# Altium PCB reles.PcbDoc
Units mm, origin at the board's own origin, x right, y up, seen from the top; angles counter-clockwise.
Board outline 127 x 101.6 mm, 2 copper layers (Top Layer, Bottom Layer); 7 components, 7 nets, 21 pads, 0 vias.
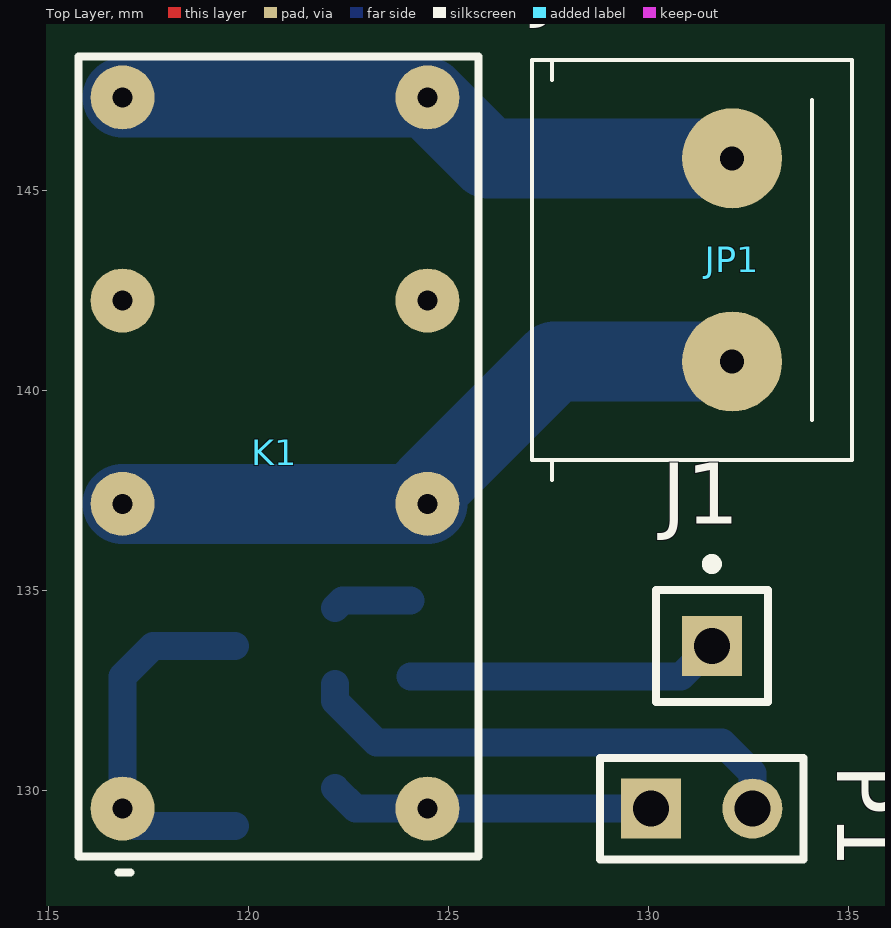
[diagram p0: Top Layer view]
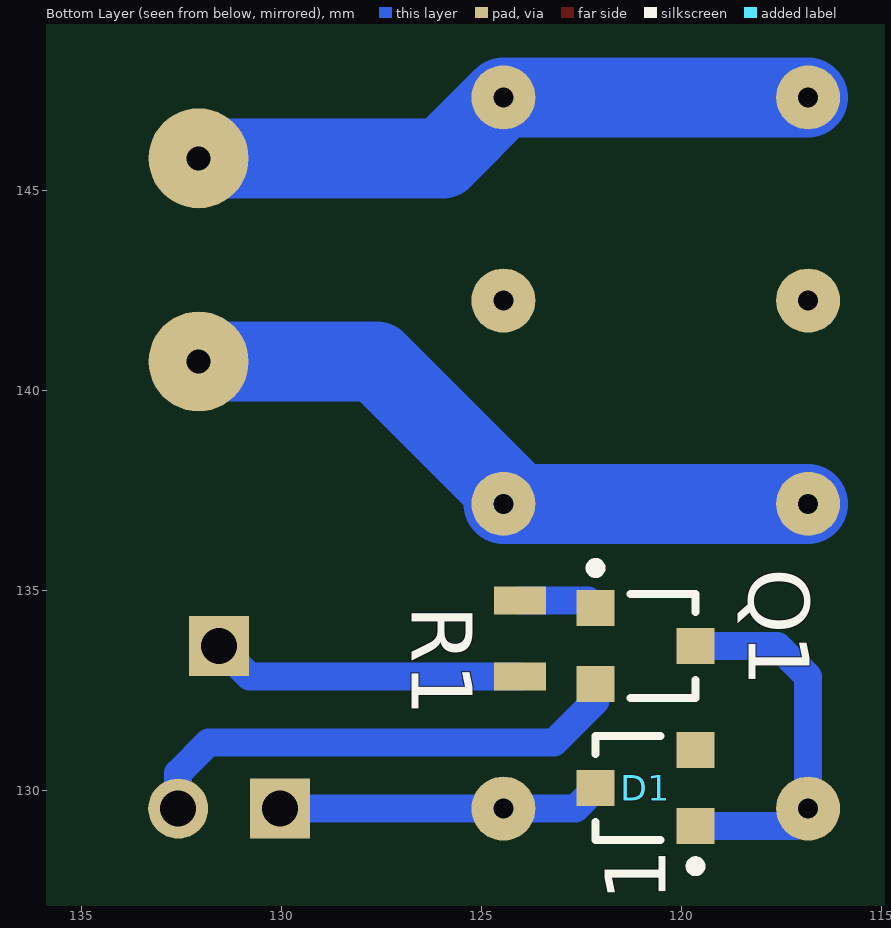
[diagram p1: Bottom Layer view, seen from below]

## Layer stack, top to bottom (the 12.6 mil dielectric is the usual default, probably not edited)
Top Layer: signal copper 0.0356
Dielectric: dielectric 0.32, FR-4, Dk 4.8
Bottom Layer: signal copper 0.0356

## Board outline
50.8,76.2 177.8,76.2 177.8,177.8 50.8,177.8

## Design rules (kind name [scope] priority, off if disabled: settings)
Clearance [All] p1: gap=0.2
ComponentClearance [All] p1: gap=0.254 collisioncheckmode=3 verticalgap=0.254
PolygonConnect [All] p1: connectstyle=Relief reliefconductorwidth=0.254 reliefentries=4 polygonreliefangle="90 Angle"
RoutingVias [All] p1: holewidth=0.6 width=1 viastyle="Through Hole" minholewidth=0.711 minwidth=1.27 maxholewidth=0.711 maxwidth=1.27
SolderMaskExpansion [All] p1: expansion=0.102
TestPointUsage [All] p1: valid=0 allowmultiple=FALSE
Testpoint [All] p1: side=15 testpointundercomponent=TRUE minsize=1.016 maxsize=2.54 preferedsize=1.524 minholesize=0 maxholesize=1.016 preferedholesize=0.813 testpointgrid=0.025 style=1023 order=0123456789
Width [All] p1: maxlimit=5 minlimit=0.2 preferedwidth=0.2 minimp=50.000000 maximp=50.000000 favimp=50.000000
18 further rules are at their usual default settings.

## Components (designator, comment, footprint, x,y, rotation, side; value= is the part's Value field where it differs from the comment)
D1 "BAS16" SOT-23 120.904,130.048 r90 bottom
J1 "Iejimas" PIN1 131.572,133.604 r0 top
JP1 "Kanalas1_1" "JP jungties Foot_print" 132.08,143.256 r90 top
K1 "Relay-DPDT" rele 116.84,129.54 r0 top
P1 "Maitinimas" HDR1X2 130.048,129.54 r0 top
Q1 "BC849" 318-08 120.904,133.604 r270 bottom
R1 "Res Semi" 0805_Ai 123.444,132.588 r90 bottom

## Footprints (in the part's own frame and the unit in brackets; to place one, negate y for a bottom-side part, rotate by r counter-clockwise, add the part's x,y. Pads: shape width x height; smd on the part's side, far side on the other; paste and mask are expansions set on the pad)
318-08 [mm] "SOT-23; 3 Leads; Body 3.0 x 2.6 mm, inc. leads (LxW max)"
  rect 0.9x0.95 smd: 1(-0.95,-1.25) 2(0.95,-1.25) 3(0,1.25)
  silkscreen extent -2.07,-1.38 1.3,1.25
0805_Ai [mm]
  rect 0.7x1.3 smd: 1(0.25,0.6) 2(2.15,0.6)
HDR1X2 [mm] "Connector; Header; 2 Position"
  rect 1.5x1.5 hole 0.9: 1(0,0)
  round 1.5 hole 0.9: 2(2.54,0)
  silkscreen extent -1.27,-1.27 3.81,1.27
"JP jungties Foot_print" [mm] "5.08mm. korpusas 8x10mm"
  round 2.5 hole 0.6: 1(-2.54,0) 2(2.54,0)
  silkscreen extent -5.5,-3 5,5
PIN1 [mm] "Connector; Plug"
  rect 1.5x1.5 hole 0.9: 1(0,0)
  silkscreen extent -1.4,-1.4 1.4,2.17
rele [mm] "Siemens 12V dual NC NO"
  round 1.6 hole 0.5: 1(7.62,7.62) 2(7.62,12.7) 3(7.62,17.78) 4(0,7.62) 5(0,12.7) 6(0,17.78) 7(0,0) 8(7.62,0)
  silkscreen extent -1.1,-1.6 8.9,18.8
SOT-23 [mm] "SOT-23; 3 Leads; Body 3.0 x 2.6 mm, inc. leads (LxW max)"
  rect 0.9x0.95 smd: 1(-0.95,-1.25) 2(0.95,-1.25) 3(0,1.25)
  silkscreen extent -2.07,-1.37 1.3,1.25

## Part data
D1: library part "Diode BAS16", "Silicon Switching Diode for High-Speed Switching"
J1: library part Plug, "Plug"
JP1: library part TB-002, "Lituojama jungtis prisukama varzteliais. 5.08mm. skyle 3.5mm"
K1: "Dual-Pole Dual-Throw Relay"
P1: library part "Header 2", "Header, 2-Pin"
Q1: library part BC849ALT1, "General Purpose Transistor NPN Silicon"
R1: "Semiconductor Resistor"

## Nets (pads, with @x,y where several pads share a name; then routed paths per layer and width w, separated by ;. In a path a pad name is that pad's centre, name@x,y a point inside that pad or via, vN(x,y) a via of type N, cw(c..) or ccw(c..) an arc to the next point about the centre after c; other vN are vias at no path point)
GND: P1.2 Q1.2 | length 12.5
  Bottom Layer w0.7: Q1.2 122.154,132.227 123.19,131.191 131.826,131.191 132.588,130.429 P1.2
NetD1_1: D1.1 K1.7 Q1.3 | length 9.7
  Bottom Layer w0.7: K1.7@116.586,129.667 117.155,129.098 D1.1 ; K1.7 116.84,132.842 117.602,133.604 Q1.3
NetJ1_1: J1.1 R1.1 | length 7.8
  Bottom Layer w0.7: R1.1 130.806,132.838 J1.1
NetJP1_1: JP1.1 K1.1 K1.4 | length 16.9
  Bottom Layer w2: K1.4 K1.1 124.46,137.541 127.635,140.716 JP1.1
NetJP1_2: JP1.2 K1.3 K1.6 | length 15.9
  Bottom Layer w2: K1.6 K1.3 125.984,145.796 JP1.2
NetQ1_1: Q1.1 R1.2 | length 2
  Bottom Layer w0.7: Q1.1 122.338,134.738 R1.2
VCC: D1.3 K1.8 P1.1 | length 8.1
  Bottom Layer w0.7: D1.3 122.662,129.54 P1.1
pads on no net: D1.2 K1.2 K1.5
